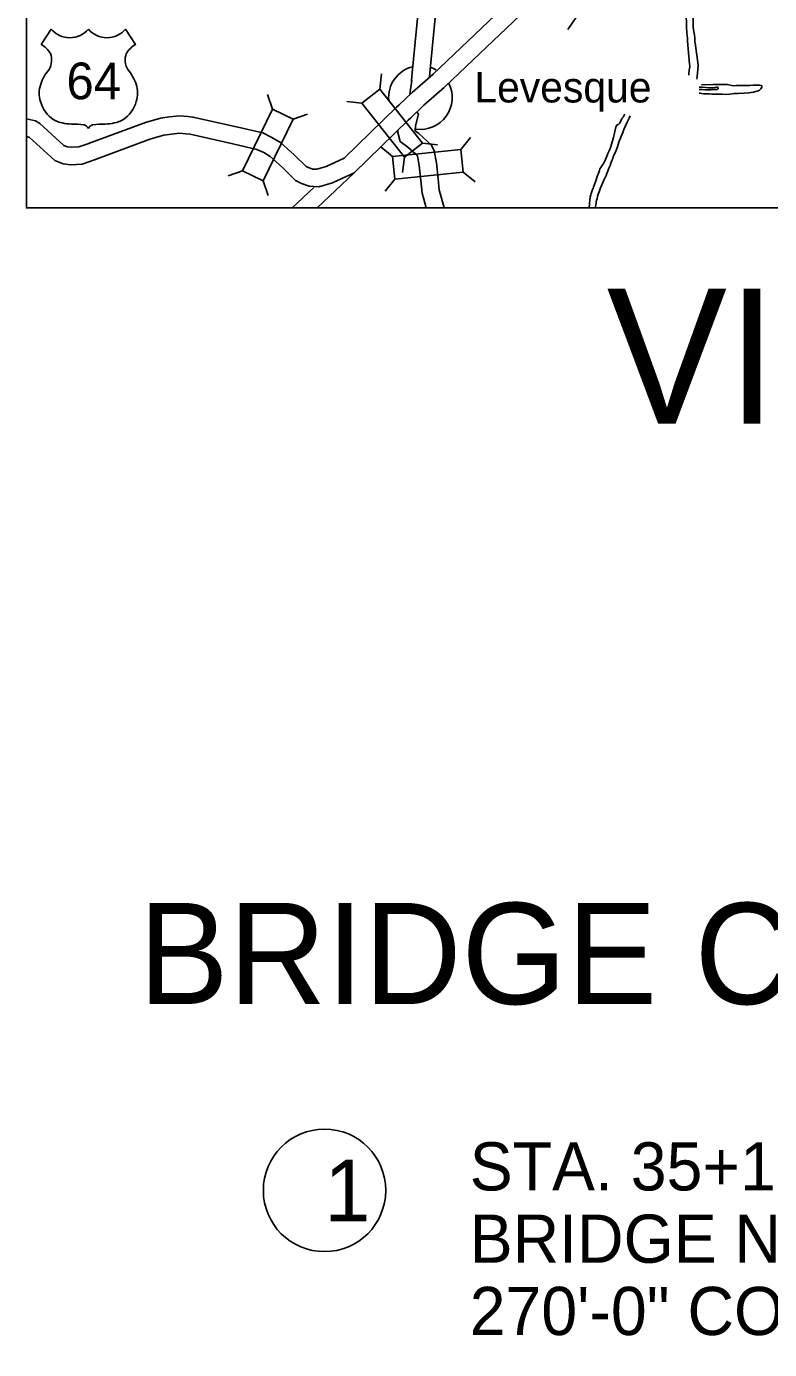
# Model space of a CAD drawing. Extents: x 1720274 to 1751788, y 372074 to 391887.
# Drawn here: x 1720610 to 1722640, y 381775 to 385389 of the extents above; entities that cross this region are included whole.
import ezdxf

# ---------------------------------------------------------------- set-up
doc = ezdxf.new("R2010")
doc.units = 0
for name, color, linetype in [('Level 10', 7, 'Continuous'), ('Level 15', 7, 'Continuous'), ('Level 20', 7, 'Continuous'), ('Level 22', 7, 'Continuous'), ('Level 24', 7, 'Continuous'), ('Level 9', 7, 'Continuous'), ('R_Draft', 7, 'Continuous')]:
    doc.layers.add(name, color=color, linetype=linetype)

msp = doc.modelspace()

# ---------------------------------------------------------------- linework, layer by layer
at = {"layer": 'Level 10'}
for points in [[(1721662.7, 385239.3), (1721663.5, 385252.6), (1721695.2, 385578.7)], [(1721711, 385251.6), (1721742.5, 385574.6)], [(1721662.9, 385241.1), (1721657.8, 385203.8)], [(1721677.9, 385153.3), (1721681.3, 385149), (1721672.8, 385116.9), (1721672.7, 385105.3), (1721673.3, 385103.1), (1721682.6, 385096.3)], [(1721625.3, 385105.5), (1721625.3, 385099.5), (1721631.7, 385074.8), (1721652.7, 385059.5)], [(1721682.6, 385096.3), (1721706.3, 385074.8), (1721717, 385064.6), (1721724.1, 385049.4), (1721730.5, 385015.9), (1721734.9, 384972.6)], [(1721652.7, 385059.5), (1721674, 385040.1), (1721677.8, 385036.5), (1721678.6, 385034.7), (1721683.5, 385009), (1721687.8, 384967.7)], [(1721505, 384988.4), (1721404.8, 384893.1)], [(1721687.8, 384967.7), (1721691.3, 384933.2), (1721695.8, 384916.8), (1721702.6, 384893.1)], [(1721734.9, 384972.6), (1721738, 384942), (1721741.5, 384929.7), (1721751.9, 384893.1)], [(1721395.1, 384949.3), (1721336, 384893.1)]]:
    msp.add_lwpolyline(points, dxfattribs=at)
at = {"layer": 'Level 15'}
for points in [[(1721720.5, 385257.5), (1721778.4, 385313.4), (1721946.3, 385472.8), (1721959, 385483.1), (1721986.2, 385499.5), (1722001.7, 385507.8), (1722018.2, 385514.2), (1722060.9, 385525), (1722081.7, 385528.9), (1722121.6, 385536.2), (1722125.2, 385536.4), (1722343.5, 385575), (1722417.6, 385587.9), (1722748.3, 385643.5), (1722994.5, 385685.3), (1723202.1, 385721.1), (1723588.5, 385787.4), (1723704, 385807.3)], [(1721753.4, 385223.4), (1721811.2, 385279.1), (1721977.7, 385437.2), (1721986.3, 385444.2), (1722009.7, 385458.3), (1722021.5, 385464.6), (1722032.6, 385468.9), (1722071.1, 385478.7), (1722090.3, 385482.3), (1722127.1, 385489), (1722130.5, 385489.2), (1722351.7, 385528.3), (1722425.5, 385541.1), (1722756.2, 385596.8), (1723002.5, 385638.6), (1723210.1, 385674.4), (1723596.5, 385740.7), (1723712, 385760.6)], [(1721478.7, 385028.9), (1721621.2, 385168.6), (1721628.9, 385174.8), (1721664.1, 385208.7), (1721721.5, 385258.4)], [(1721506, 384989.3), (1721652.9, 385133.2), (1721660.3, 385139.3), (1721696, 385173.6), (1721752.5, 385222.6)], [(1720780, 385069.1), (1720935.4, 385126.8), (1720976.3, 385138.5), (1721000.7, 385141.6), (1721028.1, 385144.6), (1721050.8, 385142.5), (1721065.1, 385141), (1721184.4, 385114.5), (1721255.8, 385098.1), (1721281, 385085.9), (1721304.8, 385071.8), (1721342.1, 385038.4), (1721374.4, 385006.5), (1721380.6, 385003.1), (1721391.6, 384999.4), (1721403.8, 384998.8), (1721429.5, 385006), (1721478.7, 385028.9)], [(1720610.3, 385136.7), (1720635.5, 385131.2), (1720646.6, 385124), (1720712.7, 385063.6), (1720722.1, 385060.1), (1720733.1, 385058.7), (1720753.1, 385059.6), (1720780.4, 385069.2)], [(1720610.3, 385088.2), (1720617, 385086.8), (1720617.5, 385086.4), (1720687.5, 385022.5), (1720710.7, 385013.8), (1720731.2, 385011.2), (1720762.2, 385012.5), (1720796.2, 385024.5)], [(1720796.5, 385024.7), (1720950.2, 385081.7), (1720985.9, 385091.9), (1721006.3, 385094.5), (1721028.5, 385097), (1721046.2, 385095.3), (1721057.5, 385094.2), (1721173.9, 385068.3), (1721239.9, 385053.1), (1721258.5, 385044.1), (1721276.6, 385033.4), (1721309.7, 385003.8), (1721345.8, 384968.2), (1721361.4, 384959.5), (1721382.7, 384952.4), (1721409.2, 384951.1), (1721446, 384961.4), (1721506, 384989.3)]]:
    msp.add_lwpolyline(points, dxfattribs=at)
at = {"layer": 'Level 20'}
for p, q in [((1722113.4, 385414.9), (1722089.5, 385380.8)), ((1721575.8, 385217.7), (1721580.7, 385259.1)), ((1721282.6, 385163.1), (1721268.9, 385202.5)), ((1721526.6, 385179), (1721485.2, 385183.9)), ((1721338.9, 385135.8), (1721378.3, 385149.5)), ((1721691.9, 385070.2), (1721733.3, 385065.2)), ((1721797.2, 385053.1), (1721823.5, 385085.5)), ((1721610.5, 385033.9), (1721578.1, 385060.3)), ((1721642.7, 385031.5), (1721637.8, 384990.1)), ((1721200.7, 384994.2), (1721161.3, 384980.5)), ((1721257, 384966.9), (1721270.7, 384927.5)), ((1721616.9, 384971.7), (1721590.5, 384939.3)), ((1721803.6, 384990.9), (1721835.9, 384964.6))]:
    msp.add_line(p, q, dxfattribs=at)
for points in [[(1721691.9, 385070.2), (1721575.8, 385217.7), (1721526.6, 385179), (1721642.7, 385031.5)], [(1721282.6, 385163.1), (1721200.7, 384994.2), (1721257, 384966.9), (1721338.9, 385135.8)], [(1721616.9, 384971.7), (1721803.6, 384990.9), (1721797.2, 385053.1), (1721610.5, 385033.9)]]:
    msp.add_lwpolyline(points, close=True, dxfattribs=at)
at = {"layer": 'Level 22'}
for p, q in [((1720677.8, 385381.7), (1720650.5, 385339.5)), ((1720881.2, 385381.7), (1720908.5, 385339.5))]:
    msp.add_line(p, q, dxfattribs=at)
for centre, radius, start, end in [((1720728.8, 385424.6), 66.6, 220.075, 319.6701), ((1720830.2, 385424.6), 66.6, 220.3299, 319.925), ((1720614.8, 385278.1), 71, 30.7809, 59.9883), ((1720944.3, 385278.1), 71, 120.0117, 149.2191), ((1720630.4, 385296.8), 48.7, 328.8105, 21.2108), ((1720928.6, 385296.8), 48.7, 158.7892, 211.1895), ((1720757.8, 385197), 113.6, 138.9565, 162.6913), ((1720801.3, 385197), 113.6, 17.3087, 41.0435), ((1720720.3, 385206.3), 75.1, 160.9576, 197.3819), ((1720838.8, 385206.3), 75.1, 342.6181, 19.0424), ((1720732.5, 385206.5), 86.9, 195.1074, 237.1312), ((1720826.5, 385206.5), 86.9, 302.8688, 344.8926), ((1720734.1, 385233.8), 111.6, 244.0771, 269.5779), ((1720736.7, 384918), 204.3, 81.1942, 90.9539), ((1720762.2, 385101.2), 19.6, 28.0342, 72.9864), ((1720796.8, 385101.2), 19.6, 107.0136, 151.9658), ((1720822.3, 384918), 204.3, 89.0461, 98.8058), ((1720824.9, 385233.8), 111.6, 270.4221, 295.9229)]:
    msp.add_arc(centre, radius, start, end, dxfattribs=at)
at = {"layer": 'Level 24'}
for start, end in [(104.1495, 185.2812), (60.0183, 71.7186), (262.3423, 26.131)]:
    msp.add_arc((1721686.6, 385194.5), 86.9, start, end, dxfattribs=at)
at = {"layer": 'Level 9'}
for points in [[(1722421.3, 385270.2), (1722422.3, 385277.8), (1722422.7, 385279), (1722422.7, 385279.3), (1722422.5, 385280.5), (1722422.6, 385282.3), (1722422.2, 385285.4), (1722416, 385348.7), (1722416.1, 385356), (1722415, 385364.2), (1722414.5, 385371.2), (1722413.4, 385387.7), (1722413.3, 385397.4), (1722413.3, 385404.2), (1722412.9, 385411.7), (1722412.1, 385422.7), (1722411.8, 385428.1), (1722412.3, 385434.1), (1722412.1, 385439.7), (1722412.2, 385444.9), (1722412.3, 385449.7), (1722412.2, 385454.4), (1722412.1, 385464.9)], [(1722444.1, 385271.5), (1722445.3, 385282.7), (1722437.2, 385344.4), (1722436.3, 385347.7), (1722436.6, 385357.1), (1722435.2, 385365.4), (1722434.7, 385369.2), (1722434, 385374.1), (1722432.5, 385381.1), (1722432.1, 385385.5), (1722431.9, 385393), (1722431.6, 385398.2), (1722432.2, 385403.6), (1722430.5, 385423.8), (1722430.2, 385429.5), (1722430.5, 385432.5), (1722430.4, 385437.6), (1722429.2, 385457.4), (1722428.9, 385460.5), (1722428.6, 385464), (1722428.4, 385467.8)], [(1722421.3, 385270.2), (1722420.2, 385257.6), (1722420, 385255.7)], [(1722444.1, 385271.5), (1722442.5, 385251.9), (1722442.5, 385249), (1722441.9, 385245.3), (1722441.8, 385244.8)], [(1722454.9, 385229.2), (1722485.5, 385229.9), (1722525.3, 385229.8), (1722540.9, 385226.9), (1722549, 385227.2), (1722556.7, 385227.7), (1722563.3, 385227.6), (1722586.3, 385227.5), (1722595.4, 385228), (1722600.7, 385228.3), (1722611.2, 385228.3), (1722614.3, 385228.1), (1722618.7, 385227.1), (1722619.3, 385226.4), (1722619.5, 385223.4), (1722618.5, 385221.4), (1722616.5, 385218.4), (1722613.4, 385214.8), (1722610.5, 385212.7), (1722606.1, 385211.8), (1722596.5, 385209.6), (1722583.5, 385207.2), (1722571.2, 385206.1), (1722554.3, 385205.8), (1722543.5, 385205.5), (1722532, 385204.2), (1722518.8, 385202.8), (1722512.3, 385203.5), (1722502.6, 385203.6), (1722492, 385203.8), (1722483.2, 385203.9), (1722475.4, 385204.3), (1722466.7, 385204.6), (1722460, 385205.1), (1722454.6, 385205.6), (1722450.7, 385206.2), (1722447.8, 385206.8)], [(1722448.5, 385216.8), (1722449.9, 385216.8), (1722452.6, 385216.8), (1722456.5, 385216.5), (1722464.6, 385215.7), (1722473.2, 385216), (1722480.1, 385216), (1722485.6, 385216.1), (1722491.8, 385216.3), (1722496, 385216.9), (1722498.5, 385217.7), (1722499.1, 385217.9), (1722499.7, 385218.4), (1722499.9, 385218.5), (1722500.3, 385219.2), (1722500.7, 385220.5), (1722500.4, 385220.9), (1722499.7, 385221.9), (1722498.4, 385222.6), (1722496.8, 385222.8), (1722490.7, 385222.1), (1722485.5, 385221.4), (1722479.7, 385221.2), (1722473.8, 385221.2), (1722465.4, 385221.8), (1722457.3, 385222.6), (1722452.9, 385222.8), (1722448.5, 385222.9)], [(1722259.8, 385144.4), (1722256.8, 385137.9), (1722255.3, 385134.6), (1722252.7, 385129.2), (1722250.5, 385125), (1722248.1, 385120.1), (1722245.8, 385114.9), (1722243.6, 385110), (1722241.8, 385105), (1722239.2, 385098.9), (1722236.8, 385092.9), (1722233.9, 385086.4), (1722232.3, 385080.9), (1722231.7, 385080.1), (1722229.1, 385073.1), (1722227, 385066.3), (1722224.9, 385059.7), (1722222.9, 385055.1), (1722220.2, 385047.7), (1722216.5, 385039.7), (1722215.1, 385036.8), (1722213.6, 385032.4), (1722212.2, 385028.2), (1722210, 385022.3), (1722207.2, 385015.4), (1722204.7, 385009.2), (1722201.5, 385001.5), (1722198.4, 384993.3), (1722197.2, 384989.5), (1722194, 384981.6), (1722190.9, 384974.7), (1722188, 384968.5), (1722185.3, 384962.5), (1722182.7, 384956.3), (1722179, 384948.3), (1722177.6, 384945.4), (1722175.7, 384940.1), (1722174.6, 384936.7), (1722172.6, 384930.4), (1722170.8, 384924.5), (1722169.2, 384919.1), (1722167.6, 384913.4), (1722166.9, 384909.6), (1722166.5, 384906.4), (1722165.7, 384901.1), (1722164.8, 384896.7), (1722164.3, 384893.1)], [(1722245.1, 385149.4), (1722245, 385149.1), (1722243.2, 385146.3), (1722242.1, 385144.6), (1722240.2, 385141.4), (1722238.2, 385138.2), (1722235.8, 385134.4), (1722234.6, 385132), (1722233.9, 385130), (1722232.8, 385127.4), (1722231.4, 385124.8), (1722230.8, 385123.8), (1722229.4, 385122.7), (1722227.6, 385121.4), (1722226.7, 385121.1), (1722225.7, 385120.9), (1722225.1, 385120.5), (1722223.9, 385119.8), (1722222.1, 385117.3), (1722220.9, 385114.9), (1722220.3, 385112.9), (1722219.6, 385109.7), (1722218.3, 385106.8), (1722216.7, 385097), (1722216.2, 385093.8), (1722215.4, 385089.9)], [(1722215.4, 385089.9), (1722213.9, 385085.1), (1722207, 385060.6), (1722205.2, 385055.2), (1722202.3, 385048.7), (1722200.7, 385045.8), (1722199.1, 385041.5), (1722196.7, 385036.3), (1722194.2, 385029.8), (1722192.7, 385025.2), (1722188, 385015), (1722185.2, 385011.4), (1722183.3, 385008.9), (1722179.9, 385003.8), (1722177, 384999.6), (1722175.5, 384995), (1722174.2, 384991.1), (1722171.8, 384985.2), (1722170.3, 384981.6), (1722169.2, 384978.6), (1722168.4, 384976.3), (1722166.4, 384969.8), (1722165, 384964.5), (1722163, 384959.8), (1722161, 384954.4), (1722159.7, 384949.5), (1722158.3, 384945.9), (1722157.2, 384943.1), (1722155.1, 384937.8), (1722153.1, 384932.4), (1722151.9, 384928.8), (1722150.6, 384922.9), (1722149.2, 384912.5), (1722148.7, 384906.9), (1722148.4, 384902), (1722147.7, 384895.3), (1722147.5, 384893.1)]]:
    msp.add_lwpolyline(points, dxfattribs=at)
at = {"layer": 'R_Draft'}
msp.add_lwpolyline([(1720610.3, 391249.6), (1726741.8, 391249.6), (1726741.8, 384893.1), (1720610.3, 384893.1)], close=True, dxfattribs=at)
msp.add_circle((1721424.7, 382210), 167.2, dxfattribs=at)

# ---------------------------------------------------------------- texts
at = {"layer": 'Level 22'}
msp.add_text('64', height=100.11, dxfattribs=at).set_placement((1720719.7, 385190))
at = {"layer": 'Level 24'}
msp.add_text('Levesque', height=83.42, dxfattribs=at).set_placement((1721834.1, 385181.1))
at = {"layer": 'R_Draft'}
for s, height, p in [('VICINITY MAP', 368.421, (1722195.6, 384303.9)), ('STA. 35+17.42 BRIDGE END ', 131.579, (1721821.3, 382209.8)), ('1', 168.4, (1721424.7, 382125.8)), ('BRIDGE NO. 07696 OVER ST. FRANCIS RIVER', 131.579, (1721821.3, 382012.4)), ('270\'-0" CONTINUOUS PLATE GIRDER UNIT (90\'-90\'-90\')', 131.579, (1721821.3, 381815))]:
    msp.add_text(s, height=height, dxfattribs=at).set_placement(p)
msp.add_text('BRIDGE CONSTRUCTION DATA', height=276.316, rotation=359.9958, dxfattribs=at).set_placement((1720916.3, 382718.9))

doc.saveas('drawing.dxf')
